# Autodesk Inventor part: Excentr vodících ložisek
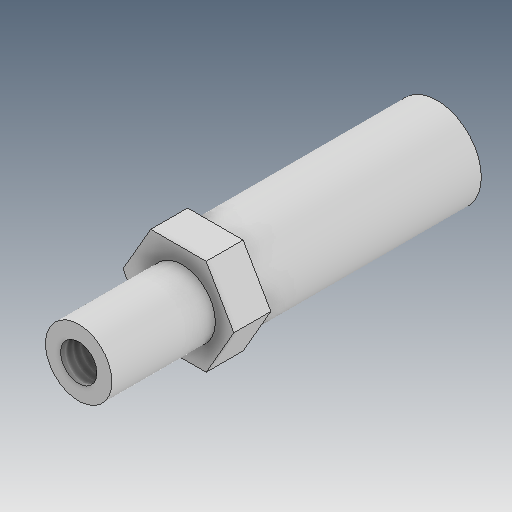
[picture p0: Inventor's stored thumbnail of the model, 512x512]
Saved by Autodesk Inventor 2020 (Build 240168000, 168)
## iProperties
Created: 2025-03
Part Number: Excentr vodících ložisek
Material: Všeobecné
Document SubType Name: Modeling
Designer: doma
Density: 1 g/cm^3
Appearance: Výchozí
Mass: 3.88784 g
Surface Area: 27.8138 cm^2
Volume: 3.88784 cm^3
Author: doma
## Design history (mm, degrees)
sketch "Náčrt1"
  geometry: C1 r 6 at (0, 0); 1 further point
  constraints: 1 centre point, 1 coincident
  dimensions: "d0" = 12 diameter of C1
extrude "Vysunutí1" new body sketch "Náčrt1" distance "d1" = 30; taper "d2" = 0 deg
sketch "Náčrt2"
  geometry: L1 (3.753, 6.5)-(7.506, 0); L2 (7.506, 0)-(3.753, -6.5); L3 (3.753, -6.5)-(-3.753, -6.5); L4 (-3.753, -6.5)-(-7.506, 0); L5 (-7.506, 0)-(-3.753, 6.5); L6 (-3.753, 6.5)-(3.753, 6.5); 2 further points
  constraints: 12 end point, 1 coincident, 13 other
  dimensions: "d3" = 13 distance between parallel lines of L3 L6
extrude "Vysunutí2" join sketch "Náčrt2" distance "d4" = 5; taper "d5" = 0 deg
sketch "Náčrt3"
  geometry: C1 r 4.5 at (0.5, 0); 1 further point
  constraints: 1 centre point
  dimensions: "d6" = 9 diameter of C1; "d7" = 0.5 distance of C1.centre point (0, 0)
extrude "Vysunutí3" join sketch "Náčrt3" distance "d8" = 14; taper "d9" = 0 deg
node "Pracovní bod1"
hole "Díra1" diameter "d12" = 4.917; stored, may be unused: countersink angle "d16" = 90 deg, drill point angle "d18" = 118 deg; dims "d13" = 12, "d14" = 14, "d15" = 8, "d17" = 17.1, "d30" = 10, "d31" = 10
node "Pracovní bod2"
hole "Díra2" diameter "d21" = 6.647; stored, may be unused: countersink angle "d25" = 90 deg, drill point angle "d27" = 118 deg; dims "d19" = 10, "d20" = 10, "d22" = 16, "d23" = 14, "d24" = 8, "d26" = 22.2
node "Těleso1"
